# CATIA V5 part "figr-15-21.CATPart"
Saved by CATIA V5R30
Part number: Part1
Bounding box of the stored display mesh (mm): x -81.56 to 85.56, y -36.965 to 25.965, z 0 to 42
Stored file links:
  D:\PROJECTS\CATIA V56R 2020\Resources\Parts File\c15_catia_v5_6r2020_prt\figr-15-21.CATPart
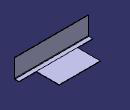
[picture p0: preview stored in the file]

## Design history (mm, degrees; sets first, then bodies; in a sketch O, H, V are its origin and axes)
SheetMetalParameters1: Thickness 1, BendRadius 1, KFactor 0.325257 {= log(min(100,max(20*SheetMetalParameters1.BendRadius,SheetMetalParameters1.Thickness)/SheetMetalParameters1.Thickness))/log(100)/2}, ReliefRadialLength 1, ReliefAxialLength 2, MinimumBendRadius 0
Body1 (main body)
  Sketch1 on xy-plane, origin (0, 0, 0), H (1, 0, 0), V (0, 1, 0)
    line L1 (-46.5596, 25.9646) -> (46.5596, 25.9646)
    line L2 (46.5596, 25.9646) -> (46.5596, -25.9646)
    line L3 (46.5596, -25.9646) -> (-46.5596, -25.9646)
    line L4 (-46.5596, -25.9646) -> (-46.5596, 25.9646)
    horizontal: L1 H, L3 H
    vertical: L2 V, L4 V
    symmetry: L1 L3 H, L4 L2 V
  Wall1: Thickness 1, Profile Sketch1
  d_NewWallOnEdge1: NewWallOnEdge_Edge edge [face of Wall1 | face of Wall1], NewWallOnEdge_Length 42, NewWallOnEdge_HeightLimitOffset 0, NewWallOnEdge_WidthOffset1 39, NewWallOnEdge_WidthOffset2 35, NewWallOnEdge_Angle 90, NewWallOnEdge_BendRadiusValue 1 {= SheetMetalParameters1.BendRadius}, NewWallOnEdge_BendTable SheetMetalParameters1, KFacteur 0.325257 {= log(min(100,max(20*d_NewWallOnEdge1.Radius,SheetMetalParameters1.Thickness)/SheetMetalParameters1.Thickness))/log(100)/2}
